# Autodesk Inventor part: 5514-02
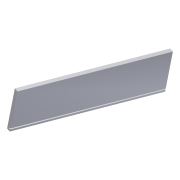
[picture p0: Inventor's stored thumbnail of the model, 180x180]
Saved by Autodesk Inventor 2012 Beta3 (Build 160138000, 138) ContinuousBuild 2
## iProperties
Created: 2011-02
Part Number: 5514-02
Material: Default
Document SubType Name: Modeling
Designer: Beta-8540w
Density: 1 g/cm^3
Author: Beta-8540w
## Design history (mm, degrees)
derived "c15-12.ipt" dims "d2" = 12.7, "d3" = 0, "d4" = 6.35, "d6" = 6.35, "d7" = 0, "width" = 444.5, "height" = 127, "thickness" = 3.302
body "Solid1"
feature "Solid1::c15-12.ipt" dims "d2" = 12.7, "d3" = 0, "d4" = 6.35, "d6" = 6.35, "d7" = 0, "width" = 444.5, "height" = 127, "thickness" = 3.302, "ScaleForDerivedMember" = 10
tag "TaggingFeature1"
